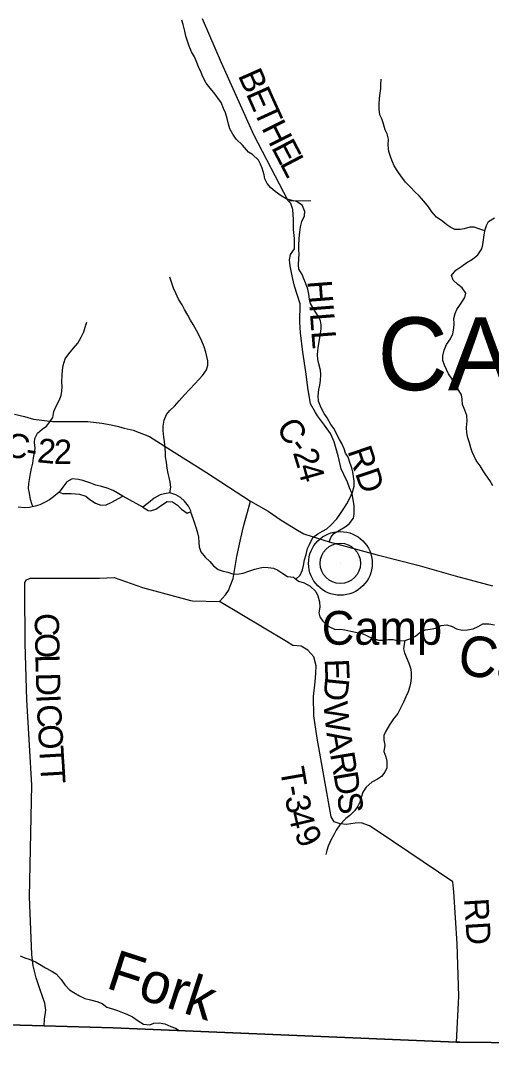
# Model space of a CAD drawing. Extents: x 1578669 to 1989827, y 208020 to 553079.
# Drawn here: x 1789632 to 1795443, y 349087 to 361904 of the extents above; entities that cross this region are included whole.
import ezdxf

# ---------------------------------------------------------------- set-up
doc = ezdxf.new("R2010")
doc.units = 0
for name, color, linetype in [('GM_X_Adjacent_County', 7, 'Continuous'), ('GM_X_County', 7, 'Continuous'), ('GM_X_County_Road', 7, 'Continuous'), ('GM_X_County_Road_Text', 7, 'Continuous'), ('GM_X_Minor_Lake', 7, 'Continuous'), ('GM_X_Minor_River', 7, 'Continuous'), ('GM_X_Minor_River_Text', 7, 'Continuous'), ('GM_X_Township', 7, 'Continuous'), ('GM_X_Township_Road', 7, 'Continuous'), ('GM_X_Township_Road_Text', 7, 'Continuous'), ('GM_X_Township_Text', 7, 'Continuous'), ('GM_X_Unincorporated', 7, 'Continuous'), ('GM_X_Unincorporated_Location', 7, 'Continuous'), ('GM_X_Unincorporated_Text', 7, 'Continuous')]:
    doc.layers.add(name, color=color, linetype=linetype)

msp = doc.modelspace()

# ---------------------------------------------------------------- linework, layer by layer
at = {"layer": 'GM_X_Adjacent_County'}
msp.add_lwpolyline([(1777594, 349890), (1782423, 349710), (1783877, 349656), (1789921, 349486), (1790774, 349462), (1795014, 349286), (1795056, 349285), (1813587, 349087)], dxfattribs=at)
at = {"layer": 'GM_X_County'}
msp.add_lwpolyline([(1813587, 349087), (1795056, 349285), (1795014, 349286), (1790774, 349462), (1789921, 349486), (1783877, 349656), (1782423, 349710), (1777594, 349890)], dxfattribs=at)
at = {"layer": 'GM_X_County_Road'}
for points in [[(1793439, 355468), (1793464, 355528), (1793500, 355570), (1793637, 355653), (1793688, 355691), (1793743, 355760), (1793751, 355810), (1793748, 355917), (1793723, 356060), (1793691, 356136), (1793666, 356206), (1793620, 356299), (1793590, 356368), (1793551, 356528), (1793526, 356617), (1793504, 356701), (1793459, 356804), (1793385, 356909), (1793296, 357022), (1793270, 357066), (1793210, 357173), (1793176, 357372), (1793153, 357569), (1793117, 357812), (1793086, 358049), (1793079, 358181), (1793081, 358406), (1793012, 358625), (1792988, 358732), (1792961, 358877), (1792950, 358949), (1792964, 359015), (1793013, 359087), (1793012, 359213), (1793001, 359324), (1793000, 359448), (1792994, 359573), (1792969, 359645), (1792933, 359679), (1792509, 360495), (1792112, 361385), (1791876, 361927)], [(1789555, 357044), (1789678, 357014), (1789791, 356983), (1790028, 356952), (1790460, 356952), (1790635, 356931), (1790748, 356911), (1790840, 356890), (1790907, 356870), (1791021, 356847), (1791221, 356767), (1791449, 356623), (1791925, 356322), (1792471, 355971)], [(1789921, 349486), (1789924, 349571), (1789941, 349680), (1789928, 349768), (1789873, 349931), (1789822, 350080), (1789787, 350231), (1789767, 350368), (1789739, 351083), (1789769, 352462), (1789762, 352599), (1789750, 352815), (1789705, 353514), (1789687, 354213), (1789681, 354884), (1789684, 354966), (1789702, 354998), (1789754, 355020), (1790603, 355020), (1790785, 355028), (1791136, 354902), (1791729, 354743), (1791751, 354740), (1792088, 354728), (1792161, 354814), (1792196, 354865), (1792257, 355013), (1792299, 355286), (1792341, 355476), (1792382, 355655), (1792432, 355835), (1792471, 355971)], [(1792471, 355971), (1792689, 355847), (1792849, 355733), (1793049, 355613), (1793129, 355565), (1793231, 355532), (1793439, 355468), (1794033, 355305), (1794534, 355180), (1794995, 355048), (1795458, 354924)]]:
    msp.add_lwpolyline(points, dxfattribs=at)
at = {"layer": 'GM_X_Minor_Lake'}
for points in [[(1791205, 355853), (1791234, 355851), (1791300, 355871), (1791370, 355919), (1791440, 355966), (1791506, 355962), (1791566, 355920), (1791618, 355872), (1791686, 355820), (1791736, 355840), (1791702, 355908), (1791654, 355970), (1791604, 356014), (1791546, 356048), (1791472, 356072), (1791406, 356062), (1791354, 356048), (1791281, 356007), (1791209, 355947), (1791141, 355897)], [(1791141, 355897), (1791205, 355853)]]:
    msp.add_lwpolyline(points, dxfattribs=at)
at = {"layer": 'GM_X_Minor_River'}
for points in [[(1791923, 361135), (1791879, 361213), (1791859, 361266), (1791829, 361334), (1791805, 361390), (1791776, 361460), (1791742, 361520), (1791712, 361592), (1791690, 361652), (1791672, 361714), (1791658, 361776), (1791638, 361857), (1791622, 361911)], [(1795363, 359309), (1795300, 359330), (1795230, 359354), (1795178, 359356), (1795110, 359332), (1795060, 359324), (1794994, 359325), (1794944, 359349), (1794893, 359385), (1794843, 359423), (1794767, 359479), (1794707, 359542), (1794667, 359604), (1794611, 359674), (1794551, 359742), (1794499, 359792), (1794445, 359850), (1794382, 359912), (1794324, 359990), (1794290, 360044), (1794244, 360112), (1794224, 360162), (1794202, 360216), (1794178, 360290), (1794170, 360367), (1794172, 360441), (1794156, 360507), (1794134, 360557), (1794108, 360643), (1794090, 360693), (1794068, 360743), (1794060, 360811), (1794059, 360870), (1794063, 360946), (1794071, 361008), (1794079, 361066), (1794081, 361116), (1794083, 361182)], [(1793031, 355005), (1793082, 355054), (1793110, 355122), (1793122, 355174), (1793136, 355244), (1793156, 355310), (1793174, 355385), (1793196, 355435), (1793238, 355519), (1793302, 355565), (1793360, 355599), (1793412, 355629), (1793466, 355676), (1793536, 355750), (1793574, 355806), (1793624, 355880), (1793660, 355938), (1793696, 356005), (1793730, 356079), (1793748, 356155), (1793750, 356217), (1793742, 356273), (1793732, 356327), (1793720, 356381), (1793702, 356436), (1793674, 356512), (1793642, 356564), (1793626, 356614), (1793596, 356680), (1793570, 356732), (1793536, 356792), (1793501, 356864), (1793463, 356918), (1793417, 357000), (1793381, 357054), (1793341, 357121), (1793311, 357203), (1793305, 357271), (1793313, 357347), (1793325, 357403), (1793333, 357459), (1793339, 357535), (1793333, 357586), (1793315, 357664), (1793299, 357718), (1793295, 357780), (1793305, 357862), (1793315, 357916), (1793325, 357988), (1793344, 358097), (1793342, 358147), (1793332, 358197), (1793306, 358255), (1793256, 358333), (1793212, 358413), (1793198, 358463), (1793188, 358525), (1793176, 358587), (1793150, 358666), (1793130, 358718), (1793106, 358768), (1793068, 358834), (1793062, 358890), (1793066, 358968), (1793070, 359022), (1793068, 359072), (1793067, 359128), (1793069, 359215), (1793077, 359291), (1793085, 359359), (1793105, 359425), (1793135, 359493), (1793139, 359548), (1793107, 359628), (1793039, 359672), (1792969, 359688), (1792919, 359700), (1792849, 359740), (1792775, 359796), (1792719, 359840), (1792675, 359894), (1792648, 359950), (1792638, 360002), (1792612, 360082), (1792592, 360132), (1792570, 360182), (1792496, 360250), (1792446, 360280), (1792370, 360368), (1792294, 360440), (1792250, 360502), (1792216, 360571), (1792199, 360627), (1792183, 360697), (1792161, 360765), (1792137, 360821), (1792105, 360893), (1792063, 360955), (1792015, 361019), (1791971, 361071), (1791923, 361135)], [(1795464, 356157), (1795426, 356223), (1795374, 356293), (1795342, 356343), (1795304, 356404), (1795258, 356470), (1795232, 356526), (1795208, 356580), (1795192, 356630), (1795172, 356692), (1795155, 356752), (1795141, 356814), (1795137, 356880), (1795145, 356961), (1795143, 357027), (1795115, 357095), (1795087, 357165), (1795085, 357231), (1795075, 357281), (1795043, 357335), (1795009, 357389), (1794969, 357465), (1794915, 357543), (1794891, 357596), (1794865, 357650), (1794846, 357706), (1794846, 357764), (1794860, 357834), (1794892, 357904), (1794940, 357976), (1794968, 358037), (1794980, 358105), (1794984, 358159), (1794982, 358227), (1794996, 358289), (1795016, 358339), (1795070, 358416), (1795116, 358484), (1795128, 358538), (1795082, 358606), (1795030, 358644), (1794972, 358698), (1794952, 358756), (1795004, 358822), (1795078, 358873), (1795142, 358919), (1795212, 358959), (1795278, 359013), (1795326, 359085), (1795338, 359140), (1795346, 359198), (1795354, 359258), (1795366, 359326), (1795382, 359376), (1795410, 359426), (1795484, 359468)], [(1791472, 356072), (1791484, 356142), (1791476, 356204), (1791466, 356260), (1791451, 356312), (1791441, 356378), (1791431, 356451), (1791421, 356517), (1791419, 356571), (1791407, 356707), (1791399, 356761), (1791391, 356843), (1791389, 356895), (1791405, 356972), (1791433, 357040), (1791475, 357090), (1791529, 357142), (1791589, 357208), (1791655, 357283), (1791715, 357349), (1791787, 357421), (1791833, 357471), (1791875, 357521), (1791925, 357590), (1791943, 357650), (1791941, 357702), (1791931, 357758), (1791917, 357810), (1791895, 357878), (1791869, 357948), (1791835, 358018), (1791803, 358077), (1791761, 358153), (1791729, 358205), (1791696, 358269), (1791656, 358337), (1791624, 358393), (1791582, 358463), (1791546, 358539), (1791520, 358599), (1791496, 358661), (1791472, 358736)], [(1789784, 355901), (1789773, 355923), (1789753, 355989), (1789738, 356069), (1789728, 356126), (1789731, 356186), (1789743, 356260), (1789754, 356312), (1789764, 356372), (1789779, 356440), (1789791, 356504), (1789802, 356566), (1789809, 356624), (1789801, 356693), (1789804, 356743), (1789838, 356810), (1789897, 356860), (1789949, 356896), (1789995, 356952), (1790030, 357003), (1790041, 357076), (1790071, 357145), (1790108, 357215), (1790130, 357273), (1790141, 357327), (1790143, 357383), (1790140, 357444), (1790144, 357524), (1790147, 357588), (1790154, 357646), (1790182, 357726), (1790227, 357788), (1790285, 357858), (1790336, 357923), (1790379, 357995), (1790411, 358063), (1790428, 358117), (1790446, 358179)], [(1790893, 356033), (1790773, 356100), (1790699, 356129), (1790629, 356149), (1790557, 356169), (1790499, 356192), (1790449, 356210), (1790399, 356224), (1790347, 356238), (1790267, 356245), (1790202, 356207), (1790150, 356143), (1790105, 356082)], [(1790105, 356082), (1790038, 356025), (1789985, 355985), (1789935, 355957), (1789867, 355925), (1789811, 355907), (1789738, 355890), (1789676, 355888), (1789600, 355896)], [(1790105, 356082), (1790146, 356064), (1790204, 356066), (1790254, 356063), (1790308, 356061), (1790358, 356056), (1790434, 356032), (1790486, 355991), (1790554, 355946), (1790622, 355922), (1790686, 355925), (1790750, 355955), (1790893, 356033)], [(1791141, 355897), (1790893, 356033)], [(1791730, 355837), (1791762, 355747), (1791778, 355697), (1791798, 355637), (1791814, 355579), (1791828, 355523), (1791832, 355457), (1791835, 355407), (1791857, 355343), (1791911, 355279), (1791969, 355223), (1792013, 355171), (1792071, 355127), (1792133, 355103), (1792191, 355091), (1792261, 355067), (1792329, 355071), (1792379, 355079), (1792449, 355103), (1792524, 355129), (1792574, 355143), (1792626, 355153), (1792686, 355151), (1792752, 355141), (1792806, 355115), (1792870, 355077), (1792926, 355039), (1793000, 355030), (1793062, 354980), (1793134, 354962), (1793206, 354920), (1793275, 354852), (1793301, 354801), (1793323, 354727), (1793325, 354661), (1793315, 354591), (1793325, 354539), (1793361, 354489), (1793437, 354423), (1793513, 354383), (1793581, 354389), (1793633, 354381), (1793707, 354365), (1793787, 354349), (1793840, 354339), (1793912, 354307), (1793980, 354271), (1794056, 354251), (1794106, 354251), (1794174, 354261), (1794232, 354262), (1794296, 354242), (1794378, 354248), (1794456, 354278), (1794506, 354300), (1794566, 354352), (1794630, 354382), (1794687, 354388), (1794759, 354402), (1794825, 354435), (1794895, 354443), (1794961, 354421), (1795013, 354391), (1795083, 354377), (1795151, 354379), (1795221, 354391), (1795283, 354423), (1795337, 354453), (1795413, 354453), (1795483, 354440)], [(1794375, 354247), (1794366, 354202), (1794360, 354147), (1794370, 354095), (1794424, 353969), (1794451, 353895), (1794455, 353843), (1794453, 353781), (1794445, 353721), (1794431, 353668), (1794417, 353612), (1794387, 353554), (1794359, 353488), (1794327, 353420), (1794289, 353346), (1794237, 353279), (1794187, 353205), (1794141, 353127), (1794117, 353075), (1794115, 353015), (1794127, 352955), (1794115, 352876), (1794139, 352812), (1794155, 352758), (1794155, 352674), (1794127, 352622), (1794089, 352568), (1794037, 352534), (1793969, 352497), (1793897, 352435), (1793855, 352375), (1793835, 352309), (1793819, 352253), (1793793, 352200), (1793757, 352148), (1793697, 352086), (1793647, 352050), (1793573, 351970), (1793529, 351906), (1793499, 351849), (1793463, 351781), (1793429, 351707), (1793411, 351655), (1793399, 351603)], [(1789624, 350354), (1789682, 350329), (1789736, 350313), (1789813, 350278), (1789865, 350249), (1789937, 350205), (1790007, 350166), (1790070, 350129), (1790130, 350061), (1790175, 349994), (1790235, 349932), (1790289, 349899), (1790356, 349858), (1790424, 349826), (1790492, 349809), (1790570, 349790), (1790636, 349764), (1790694, 349717), (1790778, 349695)], [(1790778, 349695), (1790825, 349676), (1790889, 349654), (1790943, 349633), (1791013, 349599), (1791081, 349550), (1791148, 349507), (1791226, 349501), (1791277, 349520), (1791341, 349524), (1791413, 349511), (1791484, 349481), (1791542, 349458), (1791590, 349429)]]:
    msp.add_lwpolyline(points, dxfattribs=at)
at = {"layer": 'GM_X_Township'}
msp.add_lwpolyline([(1813587, 349087), (1795056, 349285), (1795014, 349286), (1790774, 349462), (1789921, 349486), (1783877, 349656), (1782423, 349710), (1777594, 349890)], dxfattribs=at)
at = {"layer": 'GM_X_Township_Road'}
for points in [[(1792933, 359679), (1793215, 359685)], [(1795014, 349286), (1795043, 349853), (1795023, 350501), (1794979, 351144), (1794970, 351268), (1794057, 351881), (1793939, 351957), (1793837, 351997), (1793762, 351990), (1793654, 351975), (1793577, 351985), (1793501, 352010), (1793464, 352069), (1793292, 353041), (1793253, 353318), (1793249, 353555), (1793268, 353737), (1793277, 353846), (1793280, 353936), (1793251, 354047), (1793179, 354129), (1793093, 354178), (1792994, 354187), (1792912, 354234), (1792088, 354728)]]:
    msp.add_lwpolyline(points, dxfattribs=at)
at = {"layer": 'GM_X_Unincorporated'}
for radius in [393, 249]:
    msp.add_circle((1793579, 355201), radius, dxfattribs=at)
at = {"layer": 'GM_X_Unincorporated_Location'}
msp.add_line((1793579, 355201), (1793579, 355201), dxfattribs=at)

# ---------------------------------------------------------------- texts
at = {"layer": 'GM_X_County_Road_Text'}
for s, rotation, p in [('B', 293.8603, (1792310, 361230)), ('E', 293.8694, (1792409, 361004)), ('T', 294.5642, (1792502, 360795)), ('H', 296.5286, (1792600, 360581)), ('E', 297.6838, (1792721, 360339)), ('L', 297.7086, (1792825, 360141)), ('HILL', 274.4592, (1793172, 358689)), ('C', 301.115, (1792780, 356884)), ('C', 344.966, (1789414, 356546)), ('2', 354.4624, (1789827, 356451)), ('2', 359.3212, (1790039, 356431)), ('-', 307.6543, (1792929, 356642)), ('-', 350.0022, (1789680, 356476)), ('2', 287.0492, (1792991, 356570)), ('RD', 288.749, (1793664, 356591)), ('4', 285.5144, (1793045, 356395)), ('C', 271.1788, (1789802, 354584)), ('O', 271.1767, (1789807, 354338)), ('L', 271.184, (1789812, 354074)), ('D', 271.4837, (1789817, 353848)), ('I', 272.3007, (1789824, 353579)), ('C', 273.0853, (1789829, 353452)), ('O', 273.4101, (1789843, 353204)), ('T', 273.4047, (1789858, 352940)), ('T', 273.4111, (1789872, 352716))]:
    msp.add_text(s, height=300, rotation=rotation, dxfattribs=at).set_placement(p)
at = {"layer": 'GM_X_Minor_River_Text'}
for s, rotation, p in [('Camp', 352.0688, (1795011, 353834)), ('Fork', 342.0687, (1790670, 349960))]:
    msp.add_text(s, height=500, rotation=rotation, dxfattribs=at).set_placement(p)
at = {"layer": 'GM_X_Township_Road_Text'}
for s, rotation, p in [('E', 272.2034, (1793385, 354017)), ('D', 264.4946, (1793394, 353804)), ('W', 275.7513, (1793368, 353477)), ('A', 279.672, (1793406, 353109)), ('R', 279.599, (1793451, 352848)), ('T', 279.8978, (1792832, 352659)), ('D', 279.5779, (1793492, 352605)), ('3', 280.7357, (1792893, 352312)), ('-', 280.0689, (1792870, 352437)), ('S', 278.5484, (1793535, 352351)), ('4', 283.3814, (1792930, 352116)), ('9', 297.6848, (1793001, 351860)), ('RD', 273.4533, (1795108, 351057))]:
    msp.add_text(s, height=300, rotation=rotation, dxfattribs=at).set_placement(p)
at = {"layer": 'GM_X_Township_Text'}
msp.add_text('CAMP CREEK', height=900, rotation=0, dxfattribs=at).set_placement((1794038, 357340))
at = {"layer": 'GM_X_Unincorporated_Text'}
msp.add_text('Camp', height=417, rotation=0, dxfattribs=at).set_placement((1793349, 354196))

doc.saveas('drawing.dxf')
